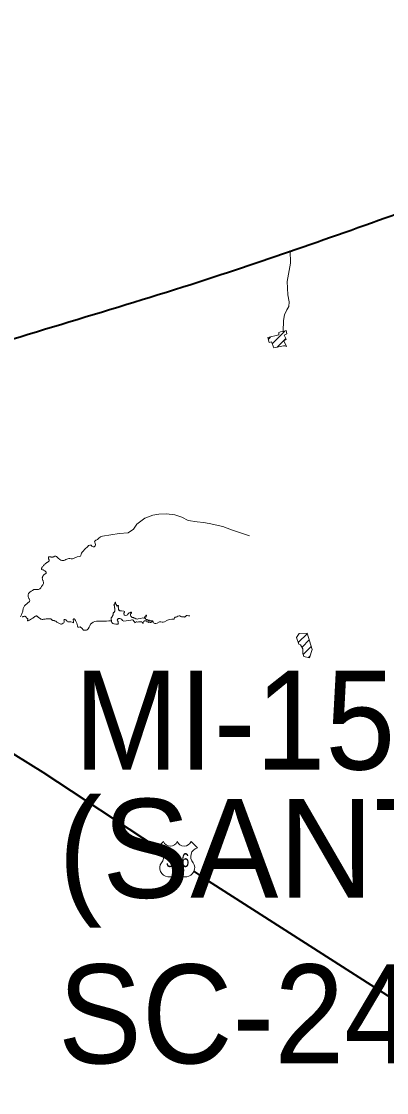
# Model space of a CAD drawing. Extents: x -1643653 to 4543381, y 1624270 to 13878484.
# Drawn here: x 598511 to 600358, y 8913574 to 8918990 of the extents above; entities that cross this region are included whole.
import ezdxf
from ezdxf.enums import TextEntityAlignment as Align

# ---------------------------------------------------------------- set-up
doc = ezdxf.new("R2010")
doc.units = 0
doc.header["$LTSCALE"] = 160
doc.layers.add('6', color=7, linetype='Continuous', lineweight=13)
doc.layers.add('60', color=7, linetype='Continuous', lineweight=13)

msp = doc.modelspace()

# ---------------------------------------------------------------- linework, layer by layer
at = {"layer": '6'}
for p, q in [((599779.1, 8917360.8), (599843, 8917424.7)), ((599760.1, 8917384.1), (599770.4, 8917394.5)), ((599804.6, 8917343.8), (599848.1, 8917387.3)), ((599850.7, 8917347.5), (599851.7, 8917348.5)), ((599911.6, 8915849.7), (599957.3, 8915895.4)), ((599930.4, 8915826.1), (599967.3, 8915863)), ((599936, 8915789.3), (599977.2, 8915830.5)), ((599963, 8915773.8), (599972, 8915782.8)), ((599197.4, 8914812), (599229.4, 8914844)), ((599369.2, 8914844), (599401.2, 8914812))]:
    msp.add_line(p, q, dxfattribs=at)
for points in [[(599871, 8917832.6), (599871.8, 8917767.7), (599854.5, 8917674.6), (599859.5, 8917608.7), (599864.6, 8917573), (599864.4, 8917548.3), (599853.3, 8917532), (599842.1, 8917507.4), (599836.4, 8917477.3), (599835.9, 8917422.3)], [(599664, 8916389.5), (599573.3, 8916420.2), (599530.2, 8916437.2), (599461.5, 8916451.1), (599431.6, 8916456.9), (599399.5, 8916459.4), (599354, 8916466.4), (599323.1, 8916483.3), (599287.7, 8916495.8), (599244.5, 8916500.6), (599205.7, 8916498.8), (599176.8, 8916494.6), (599135.6, 8916479.4), (599094.3, 8916448.7), (599077.5, 8916423.3), (599051.8, 8916404.7), (599005.2, 8916401.8), (598921.8, 8916388.1), (598911.5, 8916383.7), (598902.3, 8916377.5), (598896.6, 8916370.4)], [(598896.6, 8916370.4), (598896.5, 8916370.3), (598893.5, 8916368.7), (598887.3, 8916366.8), (598882.2, 8916362.8), (598880.8, 8916359.9), (598881.9, 8916356.9), (598884.8, 8916351.1), (598886.9, 8916345), (598886.3, 8916341.8), (598884.8, 8916338.9), (598880.1, 8916334.3), (598877, 8916333.6), (598873.8, 8916334.3), (598868.3, 8916337.8), (598863.6, 8916342.2), (598860.4, 8916342.9), (598857.1, 8916342.3), (598851.2, 8916339.6), (598846.8, 8916334.9), (598841.8, 8916330.9), (598836.5, 8916327.1), (598819.4, 8916307.3), (598815.4, 8916302.1), (598813, 8916296.2), (598811.1, 8916289.8), (598809.4, 8916287.1), (598806.8, 8916285.3), (598793.8, 8916283.8), (598781.7, 8916278.8), (598769.7, 8916273.6), (598763.3, 8916273), (598756.9, 8916274.3)], [(598756.7, 8916274.4), (598751.2, 8916275.1), (598746, 8916273.7), (598736, 8916269.2), (598731.6, 8916266.1), (598726.3, 8916264.3), (598720.8, 8916264.1), (598715.4, 8916265), (598710.1, 8916266.6), (598705.4, 8916269.2), (598697.1, 8916276.4), (598689.5, 8916284.3), (598684.8, 8916287.2), (598682.1, 8916287.3), (598679.5, 8916286.3)], [(599008.9, 8915970.5), (599005.2, 8915971.1), (599001.8, 8915970.8), (598999, 8915968.7), (598996.6, 8915966.3), (598996.6, 8915962.6), (598998.2, 8915958.4), (599000.3, 8915955.5), (599001.3, 8915951.8), (599001.6, 8915948.2), (599001.1, 8915944.2), (599000.3, 8915942.6), (598996.1, 8915942.1), (598992.9, 8915942.1), (598988.2, 8915942.4), (598980.2, 8915944.2), (598973.4, 8915946.6), (598969.4, 8915950.7), (598967.1, 8915956.6), (598965.2, 8915970.8), (598965.5, 8915975.2), (598968.9, 8915978.4), (598971.6, 8915982.3), (598974.5, 8915987), (598975.3, 8915992.3), (598975.3, 8915995.2), (598975.5, 8915998.1), (598976.8, 8916000.4), (598980.5, 8916004.1), (598983.4, 8916008.3), (598983.4, 8916013.8), (598983.2, 8916023.6), (598982.9, 8916029.1), (598982.9, 8916032.5), (598981.6, 8916036.2), (598979, 8916039.9), (598981.8, 8916043.3), (598983.7, 8916049.1), (598985.3, 8916051.4), (598985.5, 8916054.1), (598987.1, 8916053.5), (598987.4, 8916050.1), (598987.7, 8916046.6), (598989.2, 8916043.5), (598993.2, 8916037), (598994.2, 8916034.6), (598996.6, 8916034.9), (598999, 8916036.4), (599001.1, 8916036.7), (599002.9, 8916034.1), (599001.3, 8916030.1), (599001.6, 8916025.9), (599001.6, 8916022), (599003.2, 8916017.2), (599005.3, 8916012.8), (599008.7, 8916010.4), (599011.8, 8916009.8)], [(599084.8, 8915949.4), (599084.9, 8915951), (599083.9, 8915953.7), (599079.6, 8915958), (599076.2, 8915963), (599073.6, 8915964.1), (599070.4, 8915964.2), (599064.2, 8915963), (599040.7, 8915959.1), (599028.6, 8915958.6), (599023.2, 8915961.1), (599019.1, 8915965.5), (599014.9, 8915969.5), (599008.8, 8915970.5), (599002.7, 8915971), (598997.7, 8915967.7), (598996.3, 8915965.3), (598996.7, 8915962.2), (598999.3, 8915956.9), (599001.4, 8915951.3), (599001.3, 8915945.3), (599000.2, 8915942.6), (598997.3, 8915942), (598991.2, 8915942.1), (598979.4, 8915944.4), (598973.7, 8915946.4), (598969.8, 8915950.1), (598967.4, 8915955.4), (598966.2, 8915961.8), (598965.5, 8915968.6), (598965.3, 8915974.9), (598969.6, 8915979.1), (598972.8, 8915984.2), (598975.1, 8915989.6), (598975.3, 8915995.6), (598975.7, 8915998.6), (598977.4, 8916001.1), (598981.7, 8916005.3), (598983.3, 8916007.9), (598983.7, 8916010.8), (598983.3, 8916016.9), (598982.9, 8916028.8), (598982.4, 8916034.8), (598978.9, 8916039.8), (598982.5, 8916044.6), (598983.1, 8916047.6), (598984.6, 8916050.1), (598985.2, 8916053.2), (598985.8, 8916054.1), (598987.3, 8916053.4), (598987.5, 8916047.2), (598993.2, 8916036.7), (598993.7, 8916035.1), (598994.8, 8916034.4), (598997.7, 8916035.6), (599000.4, 8916036.8), (599002.7, 8916035), (599002.3, 8916032.1), (599001.2, 8916029.3), (599001.6, 8916023.2), (599003.1, 8916017.5), (599005.8, 8916012.2), (599008.3, 8916010.6), (599011.3, 8916009.8), (599017.3, 8916009.3), (599029.2, 8916008.2), (599032, 8916006.7), (599032.1, 8916004), (599029.5, 8915998.4), (599028.7, 8915992.5), (599030.6, 8915990.1), (599033.2, 8915988.5), (599038.9, 8915986.9), (599045, 8915987.8), (599047.6, 8915989.5), (599049, 8915992.2), (599049.9, 8915995.1), (599052.1, 8915996.9), (599057.1, 8916000.2), (599062.8, 8916002.2), (599065.4, 8916003.5), (599068.2, 8916003.6), (599068.2, 8916000.4), (599067.4, 8915997.6), (599062.5, 8915994.1), (599062.3, 8915988.1), (599065, 8915982.7), (599069.2, 8915978.6), (599071.7, 8915976.9), (599074.9, 8915976.9), (599077.9, 8915976.9), (599079.8, 8915974.8), (599082.2, 8915973.6), (599085.4, 8915973.6), (599090.5, 8915970.2), (599093, 8915968.8)], [(598679.3, 8915960.3), (598680.9, 8915959.6), (598684.7, 8915957.5), (598691.2, 8915953.3), (598703.5, 8915946.7), (598710, 8915943.5), (598713.4, 8915943.1), (598716.8, 8915944.3), (598723, 8915947.6), (598725.8, 8915949.9), (598727.3, 8915953), (598727.4, 8915960.1), (598726.6, 8915963.4), (598727.6, 8915964.8), (598729.4, 8915965.5), (598732.8, 8915965.5), (598736.1, 8915964.1), (598741.1, 8915959.1), (598743.6, 8915956.6), (598746.7, 8915954.8), (598753.7, 8915954.9), (598760.8, 8915955.2), (598767.5, 8915952.9), (598774, 8915950.1), (598775.1, 8915951.3), (598775, 8915953.1), (598775.4, 8915956.6), (598774.8, 8915960), (598773.3, 8915963.2), (598773.3, 8915966.7), (598776, 8915969), (598779.5, 8915968.9), (598782, 8915966.5), (598785.6, 8915960.4), (598792.2, 8915948), (598795, 8915934.1), (598795.2, 8915930.6), (598796.7, 8915927.7), (598800.2, 8915927.6), (598804.3, 8915928.3), (598807.8, 8915928.6), (598811, 8915927.6), (598816.6, 8915923.1), (598824.8, 8915912), (598825.9, 8915911.7)], [(599093, 8915968.8), (599096, 8915968.4), (599102, 8915968.8), (599113.8, 8915971.1), (599125.2, 8915974.7), (599130.8, 8915973.1), (599134.3, 8915973.4), (599135.2, 8915974), (599134.6, 8915975.3), (599134.3, 8915978.3), (599136.3, 8915980.6), (599138.7, 8915982.3), (599141.3, 8915983.6), (599141.8, 8915985), (599141.2, 8915986.4), (599141.1, 8915987.6), (599142.8, 8915987.7), (599144.3, 8915986.8), (599144.6, 8915985.5), (599142.6, 8915983.1), (599139.9, 8915977.8), (599139.2, 8915971.8), (599139.2, 8915968.8), (599141.3, 8915967), (599147.4, 8915966.3), (599150.5, 8915965.1), (599152.7, 8915963), (599152.8, 8915960), (599154.1, 8915959.1), (599155.8, 8915959.1), (599157.2, 8915961.6), (599159.7, 8915962.2), (599166.6, 8915960.2), (599172.6, 8915960.3), (599175.4, 8915959.6), (599177.1, 8915956.7), (599177, 8915955.3), (599175.6, 8915955.1), (599173.2, 8915956.8), (599167.2, 8915957.4), (599167, 8915955.9), (599168.3, 8915955.1), (599168.7, 8915953.8), (599167.5, 8915952.9), (599165.6, 8915950.8), (599162.7, 8915951.6), (599160.7, 8915953.8), (599159.3, 8915953.6), (599158.3, 8915952.4), (599155.8, 8915950.9), (599153.3, 8915952.5), (599147.8, 8915954.7), (599143.4, 8915958.7), (599137.4, 8915959.2), (599134.3, 8915959.1), (599132, 8915957.4), (599129.5, 8915955.8), (599127.7, 8915953.4), (599127.5, 8915947.2), (599127.1, 8915946.7), (599126.1, 8915947.5), (599123.5, 8915950.7), (599118.3, 8915953.7), (599112.6, 8915955.2), (599106.6, 8915954.9), (599103.8, 8915953.7), (599100.8, 8915953.5), (599094.9, 8915954.2), (599091.9, 8915954.2), (599089.1, 8915953.3), (599087.7, 8915950.6), (599084.9, 8915949.5)], [(599176.8, 8915955.2), (599177.7, 8915952.1), (599179.8, 8915949.5), (599182.3, 8915947.3), (599185.3, 8915946.2), (599191.9, 8915945.7), (599197.9, 8915948.5), (599209.9, 8915953.8), (599212.9, 8915955.1), (599216.1, 8915954.6), (599222.5, 8915953.2), (599228.9, 8915952.1), (599235.1, 8915954.3), (599246.6, 8915960.7), (599258.6, 8915965.9), (599271.5, 8915967.2), (599278, 8915967.5), (599281.5, 8915967.6), (599284.1, 8915969.1), (599286.3, 8915975.3), (599288.3, 8915977.7), (599291.6, 8915977.5), (599294.8, 8915977.3), (599297.7, 8915979), (599303, 8915982.6), (599309.2, 8915984.8), (599312.6, 8915985.5), (599315.2, 8915983.9), (599317.7, 8915981.7), (599320.7, 8915980.5), (599327.2, 8915979.6), (599333.7, 8915979.2), (599336.9, 8915978.5), (599338.4, 8915979), (599339.3, 8915980.4), (599343.9, 8915985), (599346.9, 8915986.2), (599350.2, 8915986.3), (599356.7, 8915984.8), (599363.2, 8915985.6)]]:
    msp.add_lwpolyline(points, dxfattribs=at)
for points in [[(599850.5, 8917427.2), (599834.3, 8917421.8), (599821.6, 8917421.3), (599813.8, 8917417.5), (599813.2, 8917405.3), (599758.2, 8917391.4), (599764.6, 8917366.4), (599775.7, 8917369.7), (599787.1, 8917340.2), (599836, 8917350.3), (599843.2, 8917350.2), (599852.5, 8917346.8), (599837.8, 8917375.8), (599849.5, 8917384.5), (599839.7, 8917403.4), (599853.1, 8917410)], [(599968.6, 8915772.5), (599982.2, 8915814.2), (599956.8, 8915897.3), (599915.6, 8915895.7), (599902.2, 8915874.7), (599914.8, 8915841.3), (599922.6, 8915837.8), (599935.3, 8915818.7), (599934.5, 8915793.9), (599939.4, 8915779.5)]]:
    msp.add_lwpolyline(points, close=True, dxfattribs=at)
at = {"layer": '6', "lineweight": 40}
for points in [[(596588.2, 8916457.2), (598619.5, 8915193.9), (599198.7, 8914813.4)], [(599384.5, 8914691.3), (599431.6, 8914660.4), (600961.1, 8913682.3), (601460.1, 8913331.7), (601690.5, 8912983.4), (601771, 8912890.8), (601830.7, 8912847.9), (601883.5, 8912819.1), (601916.8, 8912809.3)]]:
    msp.add_lwpolyline(points, dxfattribs=at)
at = {"layer": '6'}
for centre, radius, start, end in [((599185, 8914767.6), 46.1, 317.5721, 74.3689), ((599264.3, 8914857.4), 37.4, 200.9593, 339.0407), ((599334.3, 8914857.4), 37.4, 200.9593, 339.0407), ((599413.6, 8914767.6), 46.1, 105.6277, 222.4279), ((599255.7, 8914710.6), 44.9, 144.7373, 264.6578), ((599342.9, 8914710.6), 44.9, 275.3422, 35.2627), ((599251.3, 8914547.9), 118, 72.8937, 89.9006), ((599280.4, 8914642.6), 18.9, 357.6934, 72.9296), ((599318.2, 8914642.6), 18.9, 107.0704, 182.3065), ((599347.3, 8914547.9), 118, 90.0994, 107.1063)]:
    msp.add_arc(centre, radius, start, end, dxfattribs=at)
for points in [[(598300.5, 8917392.3), (598315.3, 8917441.1), (598255.3, 8917504.1), (598239.6, 8917592.4), (598271.1, 8917724.9), (598331, 8917860.5), (598362.6, 8917945.7), (598337.3, 8918008.8), (598271.1, 8918059.2), (598264.8, 8918122.3), (598283.7, 8918169.6), (598293.2, 8918216.9), (598258.5, 8918251.6), (598220.6, 8918330.5), (598230.1, 8918494.5), (598230.1, 8918586), (598223.8, 8918652.2), (598198.6, 8918705.8), (598223.8, 8918775.2), (598277.4, 8918895.6), (598337.3, 8919006), (598365.7, 8919135.4), (598368.9, 8919223.8), (598359.4, 8919260.4), (598397.3, 8919298.2), (598463.5, 8919374), (598532.9, 8919493.9), (598564.4, 8919569.6), (598630.7, 8919607.5), (598678, 8919639.1), (598668.5, 8919676.9), (598715.8, 8919736.9), (598775.8, 8919809.5), (598854.6, 8919853.7), (598920.8, 8919907.3)], [(598825.9, 8915911.7), (598844.6, 8915914.6), (598861.2, 8915942.1), (598891.6, 8915957.8), (598918, 8915957.8), (598966.1, 8915959.7)]]:
    msp.add_spline(points, degree=3, dxfattribs=at)
at = {"layer": '6', "lineweight": 40}
msp.add_spline([(596244.3, 8916699.1), (596768.6, 8916837.7), (598135.3, 8917279.9), (599449.7, 8917687.2), (600558.2, 8918071.1)], degree=3, dxfattribs=at)
at = {"layer": '6'}
for points in [[(598679.5, 8916286.3), (598678.8, 8916285.7), (598676.5, 8916284.7), (598673.8, 8916283), (598669.9, 8916281.6), (598665.8, 8916281.6), (598661, 8916282.2), (598658.3, 8916283.1), (598654, 8916284.1), (598650, 8916283.7), (598648.7, 8916281.8), (598648, 8916277.7), (598648, 8916275.1), (598649.7, 8916271.8), (598651.9, 8916267.3), (598651.9, 8916263), (598648.3, 8916258.8), (598644, 8916256.1), (598639.5, 8916253.8), (598636.1, 8916251.4), (598631.7, 8916247.3), (598626.6, 8916242.6), (598622.3, 8916238.7), (598618.9, 8916234.5), (598615.1, 8916228.9), (598613.5, 8916224.3), (598612.7, 8916220.8), (598614.4, 8916218.5), (598621, 8916217.1), (598626.8, 8916214.2), (598633, 8916210.8), (598635.1, 8916207.7), (598637.2, 8916203.7), (598636.7, 8916200), (598632.4, 8916196.2), (598628.8, 8916194.5), (598625.1, 8916193.8), (598621.6, 8916187.9), (598619, 8916182.7), (598617.6, 8916180), (598616.8, 8916177.7), (598616.8, 8916174.6), (598617.8, 8916170.6), (598619.8, 8916163.9), (598621.8, 8916158), (598623.8, 8916151), (598622.9, 8916145.1), (598616.7, 8916137.4), (598611.9, 8916132.6), (598609.7, 8916127.3), (598605.8, 8916120.6), (598598.2, 8916118), (598588.6, 8916117.2), (598581.9, 8916118.5), (598576.4, 8916118.5), (598572.5, 8916116.3), (598566.9, 8916112), (598560.8, 8916108.9), (598556.5, 8916105.6), (598551.7, 8916102.2), (598547.7, 8916098.3), (598545.4, 8916092.1), (598545.5, 8916088.6), (598545.5, 8916082.7), (598546.1, 8916078.2), (598549, 8916072.8), (598552.4, 8916067.2), (598554.1, 8916062.7), (598552.4, 8916057.7), (598549.3, 8916053.8), (598543, 8916049.8), (598536.7, 8916044.7), (598530.5, 8916038.6), (598524.2, 8916031), (598521.6, 8916025.1), (598519.9, 8916018.9), (598518.5, 8916009.1), (598515.9, 8915999), (598512, 8915990.6), (598510.7, 8915987.1), (598507, 8915979.5)], [(598515.9, 8915979.5), (598516.1, 8915979.6), (598518.1, 8915980.2), (598522.2, 8915981.3), (598526.3, 8915982.8), (598531.6, 8915982.8), (598534.6, 8915979.2), (598536.3, 8915976.7), (598537.6, 8915975.5)], [(598537.6, 8915975.5), (598538.8, 8915974.2), (598541.8, 8915971.8), (598544.6, 8915968.8), (598543.2, 8915964.3), (598541, 8915961), (598541.6, 8915958.6), (598545.1, 8915959.2), (598551.8, 8915962.7), (598562.2, 8915968), (598577.8, 8915978.9), (598582.3, 8915982.7), (598585.4, 8915984.9), (598588.7, 8915984.2), (598592.3, 8915981.1), (598595.8, 8915977.2), (598600.7, 8915975), (598605.8, 8915971.6), (598609.7, 8915968.4), (598613.4, 8915967.2), (598617.7, 8915966.8), (598623, 8915967.3), (598628.1, 8915968.3), (598636.4, 8915968.8), (598645.4, 8915970), (598654.4, 8915969.8), (598659.8, 8915969.2), (598663.5, 8915966.9), (598667.4, 8915963), (598671, 8915961), (598675, 8915960.6), (598677.9, 8915960.6), (598679.3, 8915960.3)]]:
    msp.add_open_spline(points, degree=3, dxfattribs=at)
at = {"layer": '60', "lineweight": 25}
msp.add_spline([(814781, 9009175.5), (814787.2, 9009173.4), (814796.9, 9009173.4), (814799.4, 9009172.4), (814805.1, 9009174.5), (814805.6, 9009176.5), (814811.7, 9009179.5), (814811.7, 9009179.5), (814801.5, 9009181), (814790.7, 9009181.5), (814784.1, 9009183.1), (814777.4, 9009185.1), (814778.4, 9009175.5)], degree=3, dxfattribs=at)

# ---------------------------------------------------------------- texts
at = {"layer": '6', "width": 0.95}
for s, p in [('MI-1522', (598778.2, 8915207.6)), ('SC-24-X-D-I', (598696.7, 8913722.1))]:
    msp.add_text(s, height=500, dxfattribs=at).set_placement(p)
at = {"layer": '6'}
msp.add_text('(SANTANA DO IPANEMA)', height=500, dxfattribs=at).set_placement((598696.7, 8914559.1))
at = {"layer": '6', "width": 0.75}
msp.add_text('316', height=70, dxfattribs=at).set_placement((599301.3, 8914714.4), align=Align.CENTER)

doc.saveas('drawing.dxf')
